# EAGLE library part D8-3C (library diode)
4 DIODES SIL, cathode marked
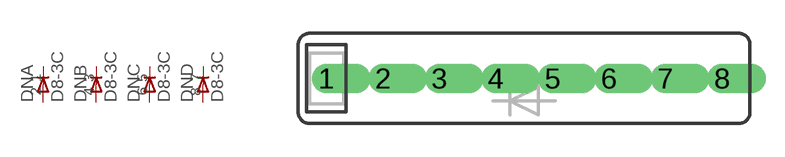
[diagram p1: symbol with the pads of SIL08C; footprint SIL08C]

Designator prefix DN; gates A=DN B=DN C=DN D=DN

## D8-3C  [SIL08C]
1  A:C  pas
2  A:A  pas
3  B:C  pas
4  B:A  pas
5  C:C  pas
6  C:A  pas
7  D:C  pas
8  D:A  pas

## Footprint SIL08C (pad centres in mm)
7 DIODES single in line 7 diodes with common cathode
drill 0.813 offset: 1 -8.89,0; 2 -6.35,0; 3 -3.81,0; 4 -1.27,0; 5 1.27,0; 6 3.81,0; 7 6.35,0; 8 8.89,0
